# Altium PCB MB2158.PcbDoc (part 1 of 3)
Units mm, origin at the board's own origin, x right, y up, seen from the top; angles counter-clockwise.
Board outline 43 x 60 mm, 4 copper layers (Top Layer, Signal Layer 1, Signal Layer 2, Bottom Layer), stack 1.539 mm thick; 117 components, 89 nets, 427 pads, 621 vias.
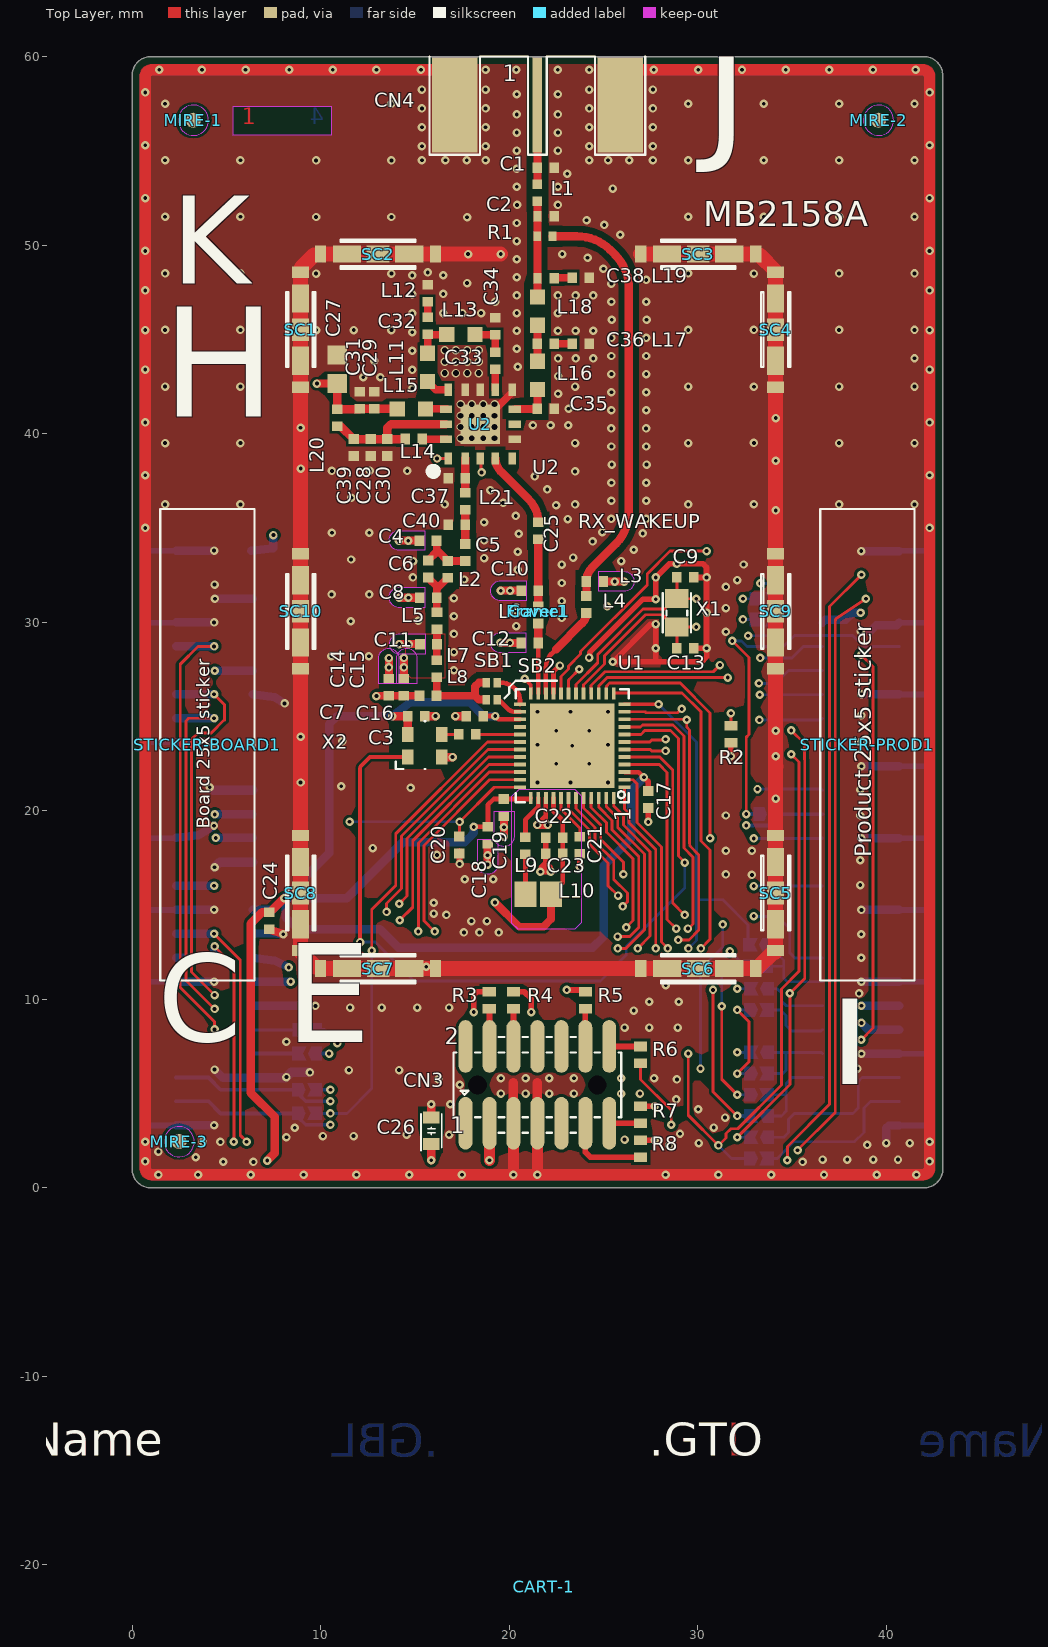
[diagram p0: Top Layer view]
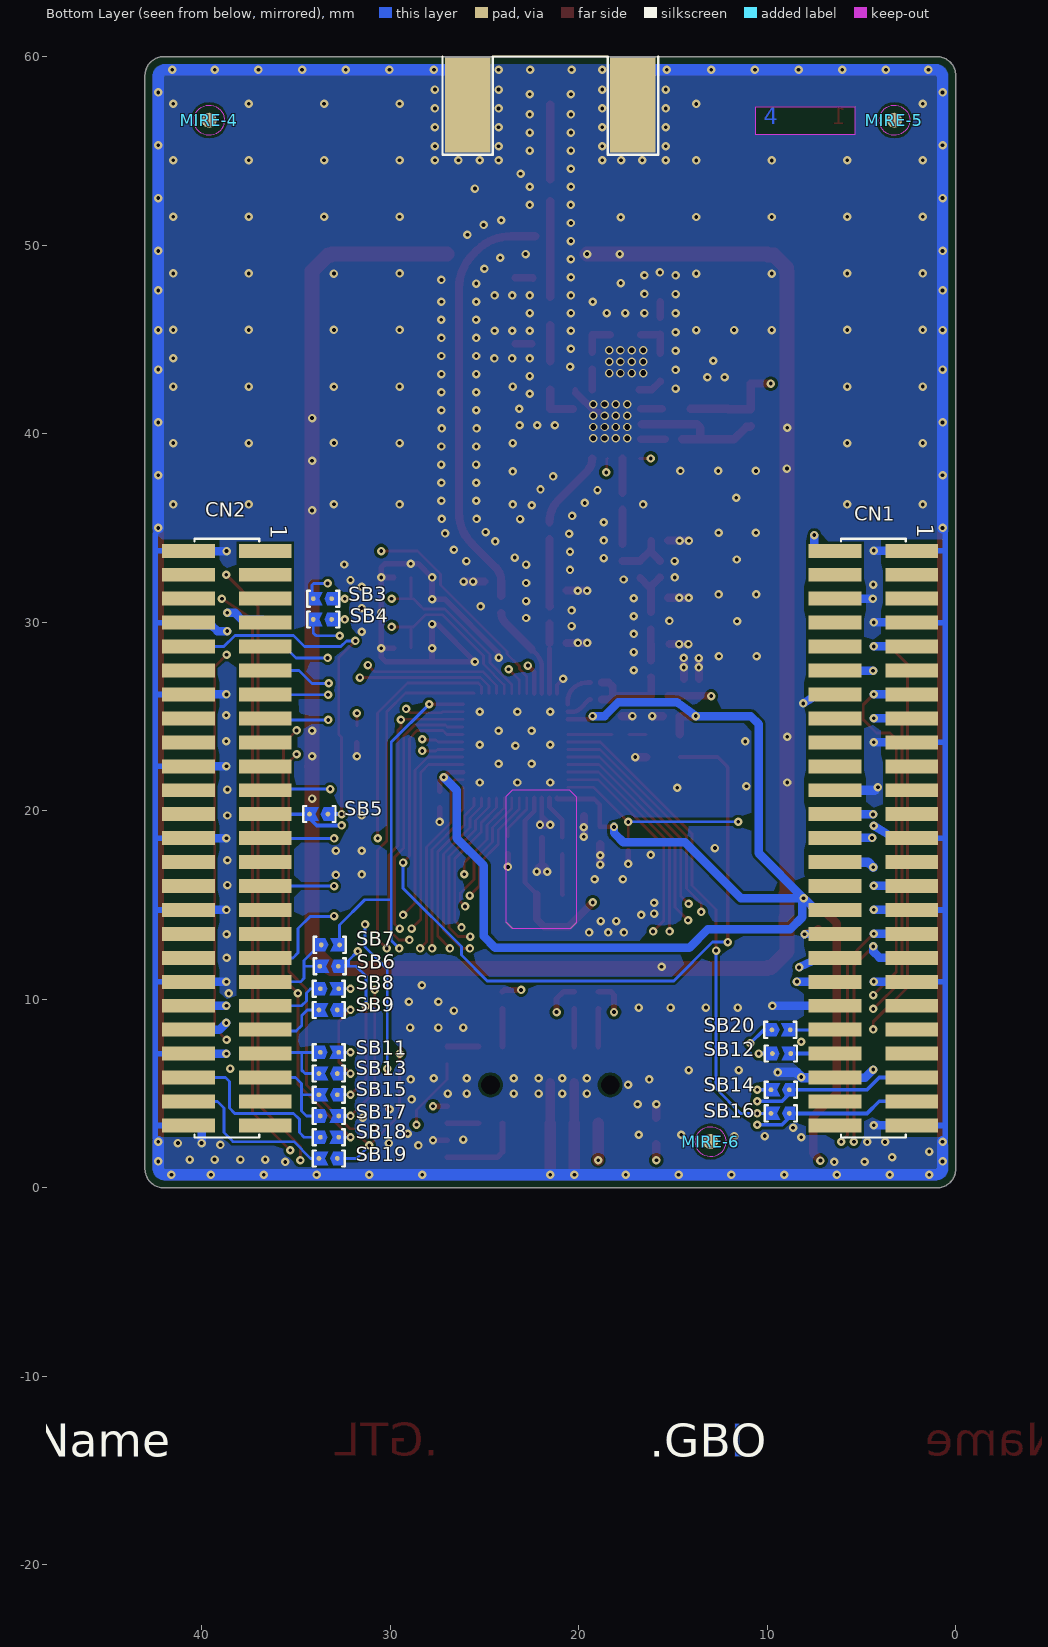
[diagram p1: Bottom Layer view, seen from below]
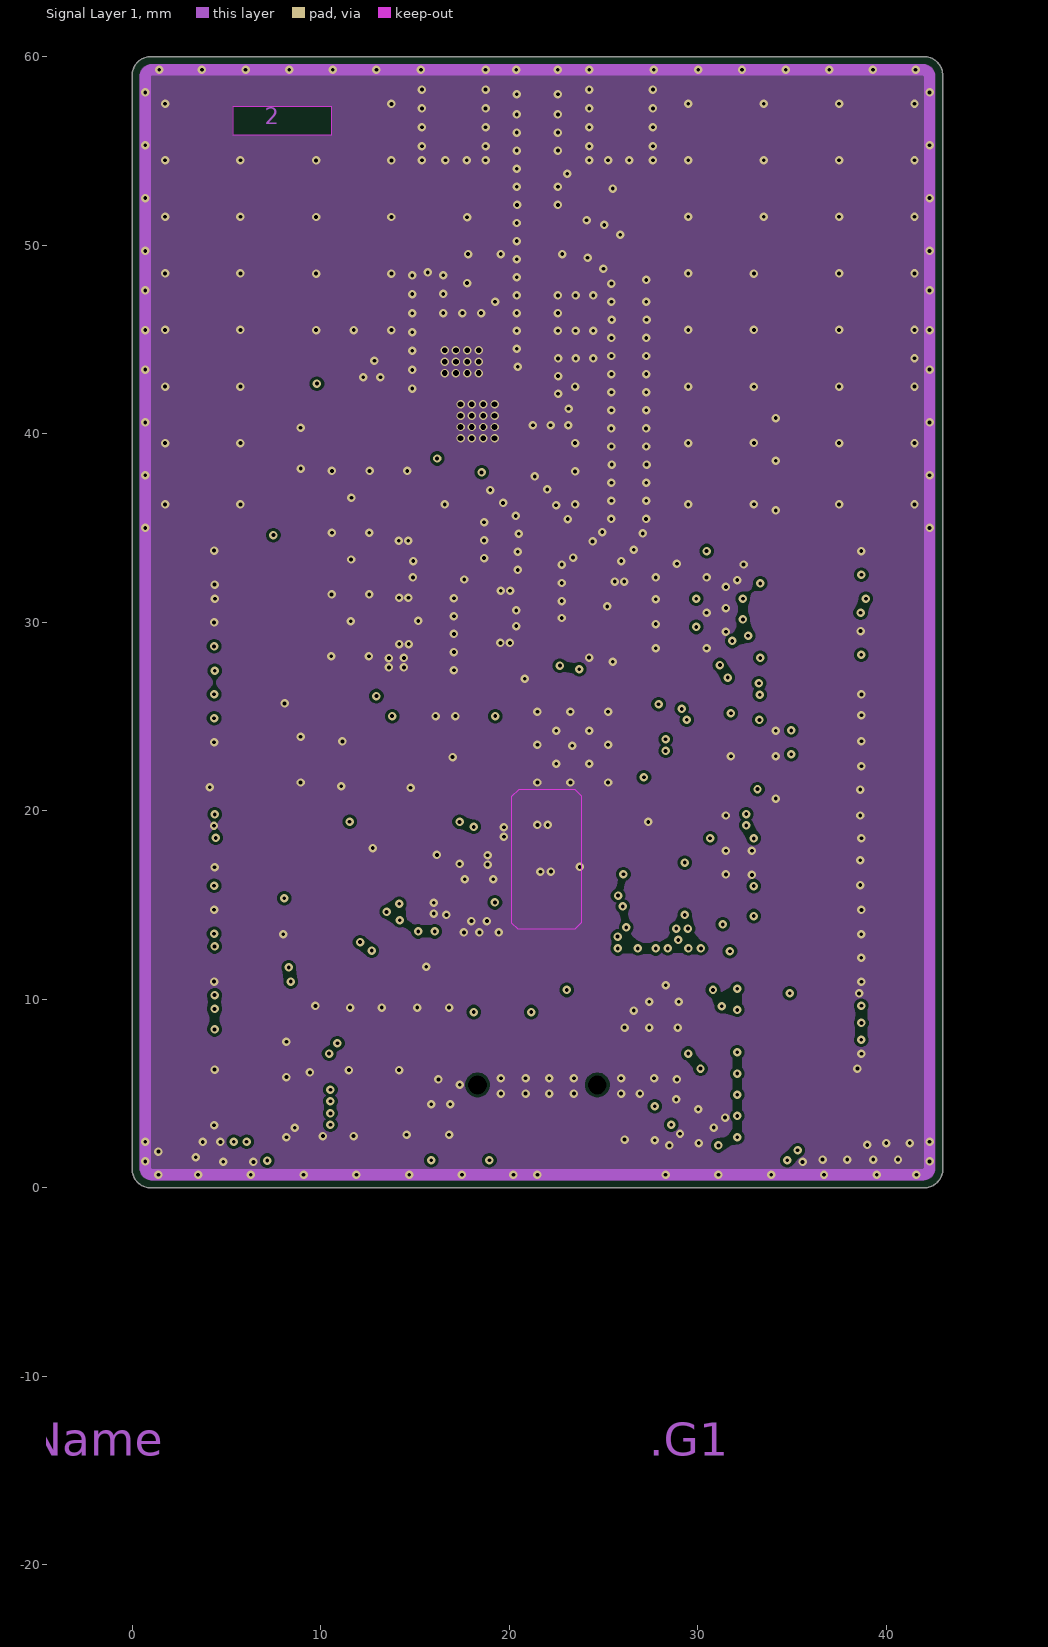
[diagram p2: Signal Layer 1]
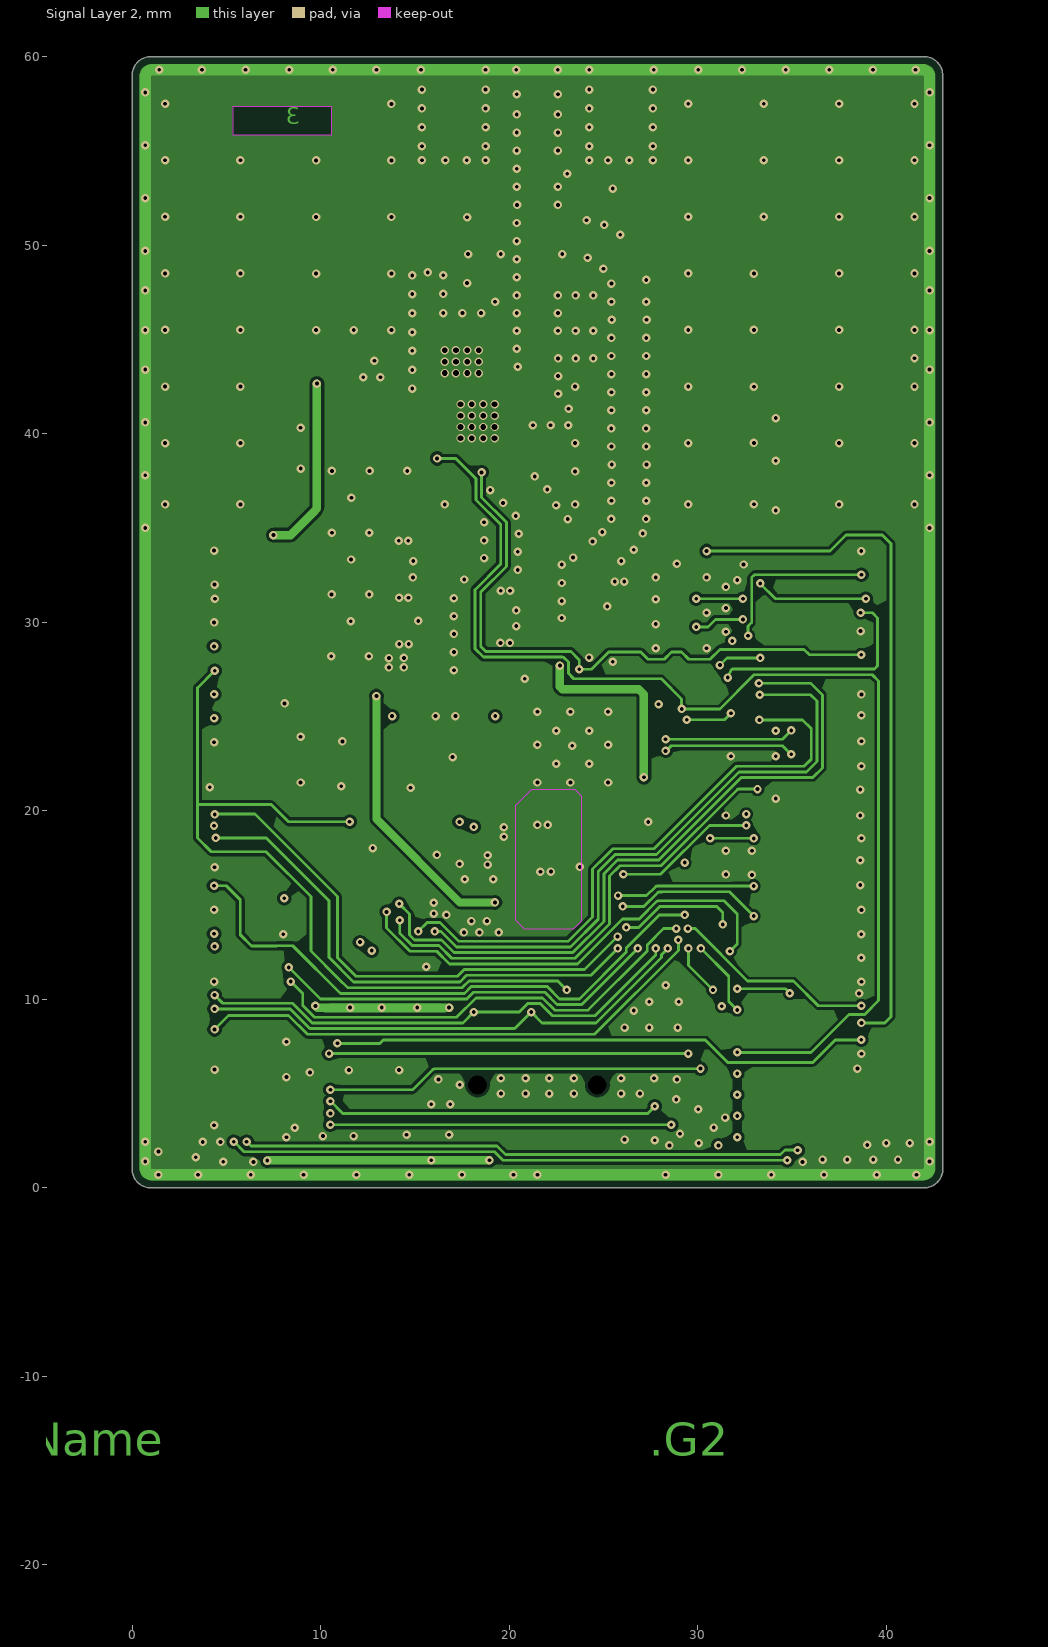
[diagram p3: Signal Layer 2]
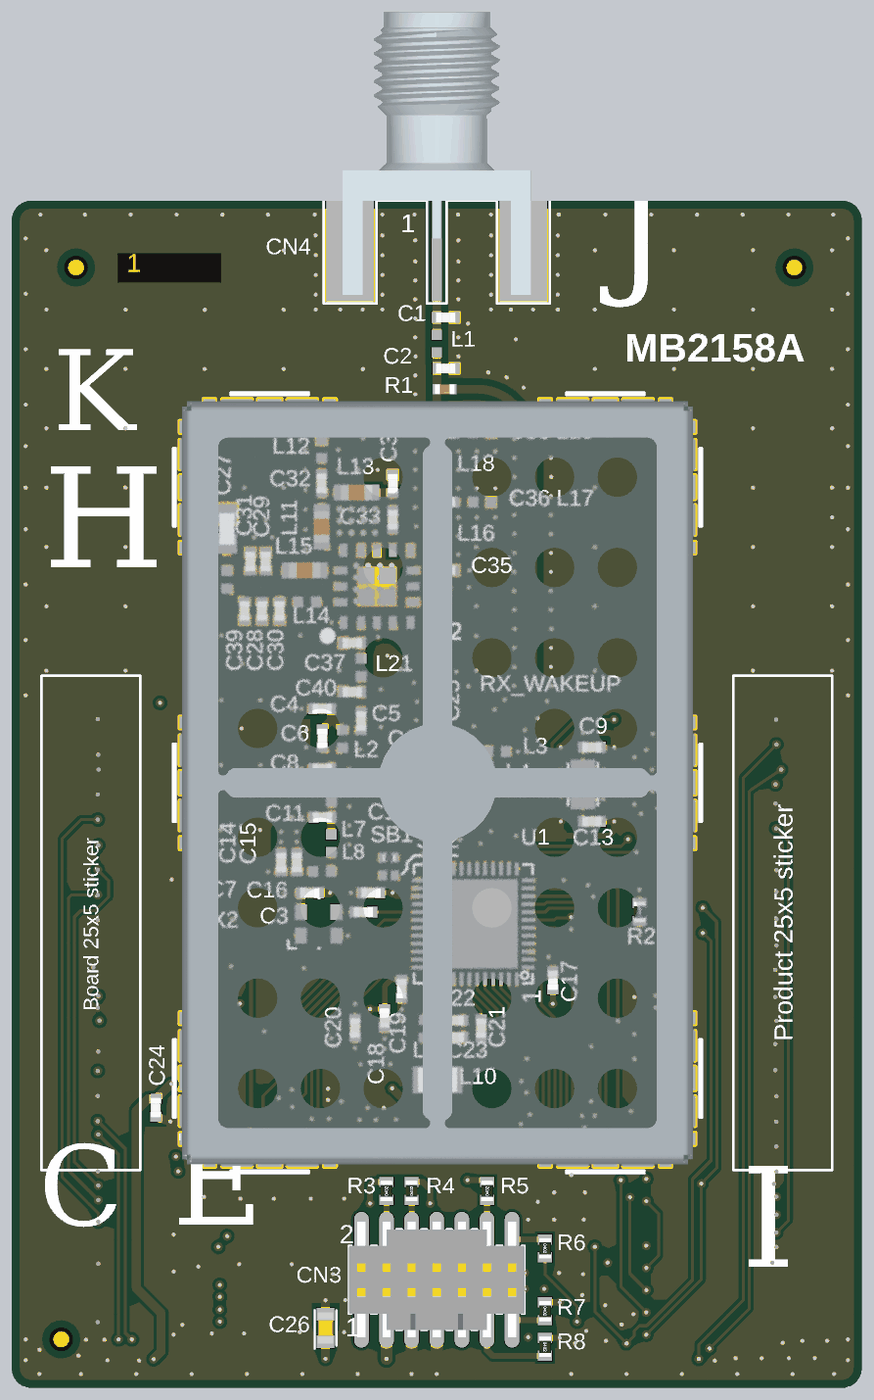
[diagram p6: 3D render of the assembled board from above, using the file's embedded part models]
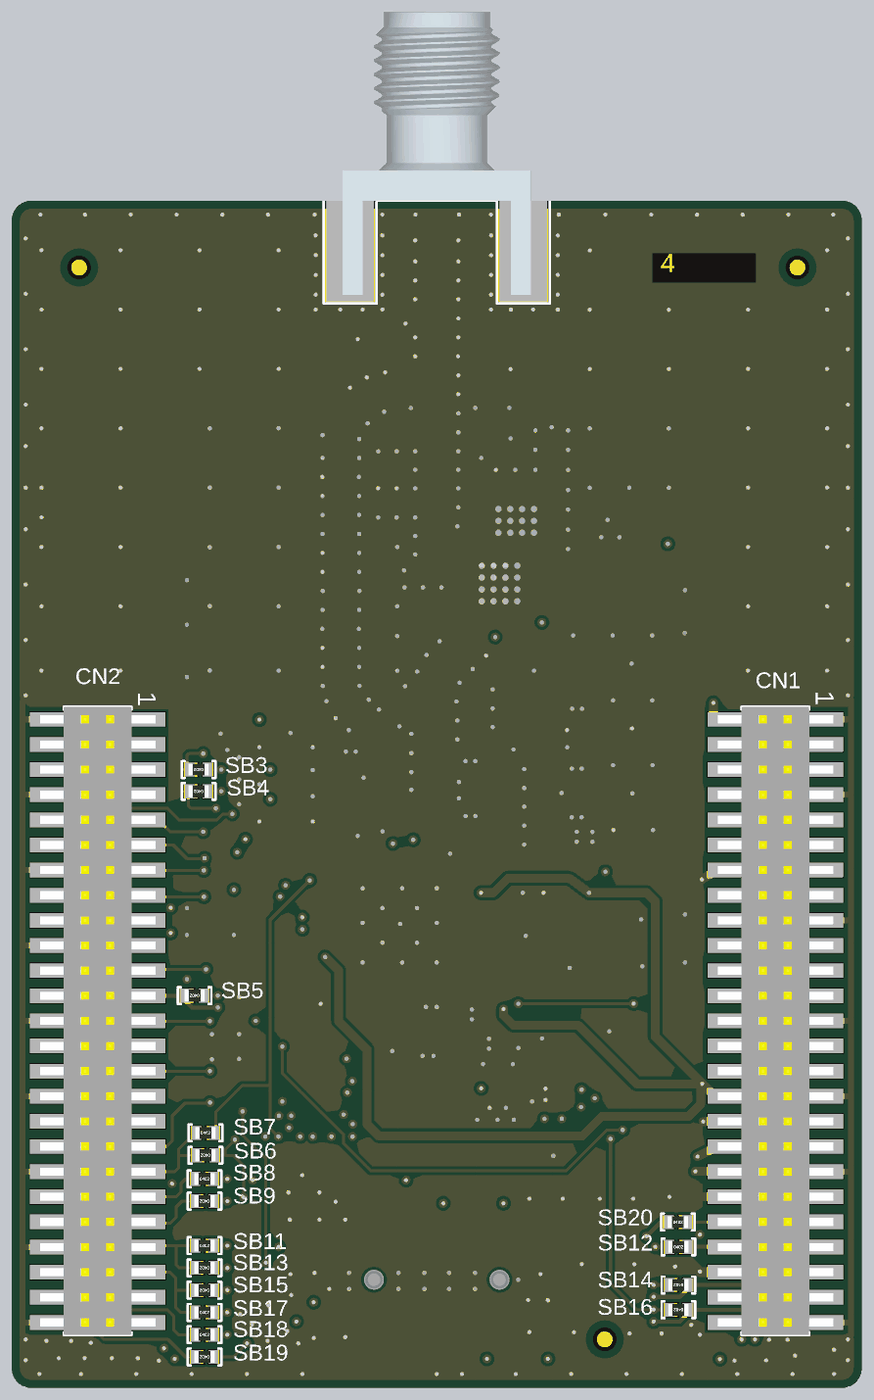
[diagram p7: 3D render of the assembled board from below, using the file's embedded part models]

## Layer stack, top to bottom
Top Solder: solder mask 0.0102, Solder Resist, Dk 3.5
Top Layer: signal copper 0.0406
Dielectric 1: core 0.254, FR4 VT-47, Dk 4
Signal Layer 1: signal copper 0.0178
Dielectric 2: core 0.9144, FR4 VT-47, Dk 4.3
Signal Layer 2: signal copper 0.0178
Dielectric 3: core 0.254, FR4 VT-47, Dk 4
Bottom Layer: signal copper 0.0406
Bottom Solder: solder mask 0.0102, Solder Resist, Dk 3.5

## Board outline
0,1 ccw(c1,1) 1,0 42,0 ccw(c42,1) 43,1 43,59 ccw(c42,59) 42,60 1,60 ccw(c1,59) 0,59

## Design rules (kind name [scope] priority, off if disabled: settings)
BoardOutlineClearance [All] p1: gap=0.4 ignorepadtopadclearanceinfootprint=FALSE
Clearance Clearance_Keepout [All vs IsKeepOut] p1: gap=0.15 ignorepadtopadclearanceinfootprint=TRUE except(0: Poly-Region)
Clearance Clearance_RF-50R [InNetClass('NC_RF-50R')] p2: gap=0.335 ignorepadtopadclearanceinfootprint=FALSE except(0.15: Arc-Arc Arc-Track Arc-SMDPad Arc-Via Track-Track Track-SMDPad Track-Via SMDPad-Via Via-Via Via-Fill Via-Region Via-Text Via-Hole; 0.2: SMDPad-SMDPad)
Clearance Clearance_Default_Same-net_GND [InNet('GND')] p3: gap=0.15 ignorepadtopadclearanceinfootprint=TRUE except(0: SMDPad-Via SMDPad-Hole Via-Via; 0.1: Arc-SMDPad Track-SMDPad Via-Hole; 0.12: SMDPad-SMDPad)
Clearance Clearance_Default_Same-net [All] p4: gap=0.15 ignorepadtopadclearanceinfootprint=TRUE except(0.1: Via-Via; 0.12: Arc-SMDPad Track-SMDPad SMDPad-SMDPad)
Clearance Clearance_Default [All] p5: gap=0.15 ignorepadtopadclearanceinfootprint=FALSE
ComponentClearance [All] p1: gap=0.165 collisioncheckmode=3 verticalgap=0.165 showdistances=FALSE
HoleSize [All] p1: absolutevalues=TRUE maxlimit=10 minlimit=0.025 maxpercent=80.000 minpercent=20.000
MinimumSolderMaskSliver [All] p1: minsoldermaskwidth=0.1
PlaneConnect [All] p1: planeconnectstyle=Relief reliefexpansion=0.508 reliefentries=4 reliefconductorwidth=0.21 reliefairgap=0.21
PolygonConnect PolygonConnect_PA [TouchesRoom('RoomDefinition')  or TouchesRoom('RoomDefinition_1') or TouchesRoom('RoomDefinition_2')or  TouchesRoom('RoomDefinition_3')or  TouchesRoom('RoomDefinition_4')] p1: connectstyle=Direct reliefconductorwidth=0.3 reliefentries=4 polygonreliefangle="90 Angle" airgapwidth=0.25
PolygonConnect [All] p2: thpad.connectstyle=Direct thpad.reliefconductorwidth=0.254 thpad.reliefentries=4 thpad.polygonreliefangle="90 Angle" thpad.airgapwidth=0.254 smdpad.connectstyle=NoConnect smdpad.reliefconductorwidth=0.254 smdpad.reliefentries=4 smdpad.polygonreliefangle="90 Angle" smdpad.airgapwidth=0.254 via.connectstyle=Direct via.reliefconductorwidth=0.254 via.reliefentries=4 via.polygonreliefangle="90 Angle" via.airgapwidth=0.254
RoomDefinition [False vs False] p1: confinementstyle=ConfineIn formatcopy=TRUE lockcomponents=FALSE outline 8.289,49.929 35.214,49.929 35.214,34.798 8.289,34.798
RoomDefinition RoomDefinition_3 [False vs False] p2: confinementstyle=ConfineIn formatcopy=TRUE lockcomponents=FALSE outline 33.125,34.4 35.139,34.4 35.139,26.625 33.125,26.625
RoomDefinition RoomDefinition_2 [False vs False] p3: confinementstyle=ConfineIn formatcopy=TRUE lockcomponents=FALSE outline 26.35,19.35 35.564,19.35 35.564,11 26.35,11
RoomDefinition RoomDefinition_1 [False vs False] p4: confinementstyle=ConfineIn formatcopy=TRUE lockcomponents=FALSE outline 7.925,34.4 9.939,34.4 9.939,26.625 7.925,26.625
RoomDefinition RoomDefinition_4 [False vs False] p5: confinementstyle=ConfineIn formatcopy=TRUE lockcomponents=FALSE outline 7.754,19.35 16.536,19.35 16.536,11 7.754,11
RoutingVias RoutingVias_Default [All] p1: holewidth=0.3 width=0.6 viastyle="Through Hole" minholewidth=0.3 minwidth=0.6 maxholewidth=0.3 maxwidth=0.6 useviatemplates=TRUE viatemplateguid#1={4832C824-464C-45B0-9914-ADACDA891A13} viatemplateguid#2={A0866A0D-D653-4B5A-8CD1-50116DFB51F8} viatemplatename#1=v45h20m0mx0 viatemplatename#2=v45h30m0mx0
SilkToSilkClearance [All] p1 off: silktosilkclearance=0.2
SilkToSolderMaskClearance [IsPad] p1 off: minsilkscreentomaskgap=0.2 clearancetoexposedcopper=TRUE
SolderMaskExpansion [All] p1: expansion=0.102 istentingtop=FALSE
ViasUnderSMD [InPadClass('PC__VIAS-IN-PAD')] p1: allowed=TRUE
Width Width_RF-50R [InNetClass('NC_RF-50R')] p1: maxlimit=0.45 minlimit=0.25 preferedwidth=0.254 toplayer_prefwidth=0.44 impedanceprofiledriven=TRUE impedanceprofileid={AD1550EC-3D0E-4E34-9E21-FD44D1EEEC04} impedanceprofilevalue=50.000000 minimp=50.000000 maximp=50.000000 favimp=50.000000
Width Width_Default [All] p2: maxlimit=10 minlimit=0.15 preferedwidth=0.2
24 further rules are at their usual default settings.

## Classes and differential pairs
pad class PC__VIAS-IN-PAD: U1- U1-49
net class NC_RF-50R: "ANT Path" NetC1_2 NetC4_2 NetC6_1 NetC11_2 NetC25_2 NetC35_2 NetC36_2 NetC37_2 NetL3_1 NetL7_1 NetSB1_1 NetSB2_1 "RX Path" "TX Path"

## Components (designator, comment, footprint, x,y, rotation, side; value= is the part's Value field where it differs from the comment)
C1 "Capacitor" C0402#1 21.95,54.1 r180 top value=TBD
C2 "Capacitor" C0402#2 21.95,51.525 r180 top value=TBD
C3 "Capacitor" C0402#1 17.787,24.05 r180 top value=1nF
C4 "Capacitor" C0402#1 15.7,34.325 r0 top value=TBD
C5 "Capacitor" C0402#1 17.675,33.7 r270 top value=TBD
C6 "Capacitor" C0402#1 15.711,32.825 r90 top value=TBD
C7 "Capacitor" C0402#1 15.077,25.025 r180 top value=10nF
C8 "Capacitor" C0402#1 15.711,31.3 r0 top value=TBD
C9 "Capacitor" C0402#1 29.35,32.375 r180 top value=6.8pF
C10 "Capacitor" C0402#1 21.1,31.675 r0 top value=TBD
C11 "Capacitor" C0402#1 15.725,28.841 r0 top value=TBD
C12 "Capacitor" C0402#1 21.09,28.9 r0 top value=TBD
C13 "Capacitor" C0402#1 29.35,28.625 r180 top value=6.8pF
C14 "Capacitor" C0402#1 13.625,26.55 r90 top value=100pF
C15 "Capacitor" C0402#1 14.42,26.555 r270 top value=100nF
C16 "Capacitor" C0402#1 18.175,25.025 r0 top value=100nF
C17 "Capacitor" C0402#1 27.375,20.6 r90 top value=100nF
C18 "Capacitor" C0402#1 18.857,18.696 r90 top value=4.7uF
C19 "Capacitor" C0402#1 19.725,20.175 r90 top value=100nF
C20 "Capacitor" C0402#1 17.365,18.183 r90 top value=100nF
C21 "Capacitor" C0402#1 23.75,18.175 r90 top value=220nF
C22 "Capacitor" C0402#1 22.391,18.572 r0 top value=4.7uF
C23 "Capacitor" C0402#1 22.391,17.722 r180 top value=100nF
C24 "Capacitor" C0402#1 7.286,14.165 r90 top value=4.7uF
C25 "Capacitor" C0402#1 21.55,34.85 r90 top value=2.2nF
C26 "Capacitor" C0603 15.875,3.025 r270 top value=1uF
C27 "Capacitor" GRM185C80J475ME11D 10.881,43.416 r90 top value=4.7uF
C28 "Capacitor" C0402#1 12.659,39.267 r270 top value=1nF
C29 "Capacitor" C0402#1 12.844,41.767 r90 top value=1uF
C30 "Capacitor" C0402#1 13.548,39.267 r270 top value=DNI
C31 "Capacitor" C0402#1 12.068,41.767 r90 top value=4.7nF
C32 "Capacitor" C0402#1 15.675,45.718 r270 top value=82pF
C33 "Capacitor" C0402#1 19.275,43.875 r90 top value=2.2nF
C34 "Capacitor" C0402#1 19.275,45.7 r270 top value=27pF
C35 "Capacitor" C0402#1 21.95,41.322 r180 top value=22pF
C36 "Capacitor" C0402#1 21.95,44.768 r180 top value=18pF
C37 "Capacitor" C0402#1 17.225,37.643 r0 top value=DNI
C38 "Capacitor" C0402#2 21.95,48.254 r180 top value=DNI
C39 "Capacitor" C0402#1 11.77,39.267 r270 top value=1uF
C40 "Capacitor" C0402#1 17.225,35.173 r0 top value=22pF
CART-1 "Comment" Sheetbox_4L2S -23.25,-26.5 r0 top
CN1 "FTSH-125-02-L-DV" CON_SAMTEC_FTSH-125-02-L-DV_INV 4.366,18.548 r270 bottom locked value="Header 25x2"
CN2 "FTSH-125-02-L-DV" CON_SAMTEC_FTSH-125-02-L-DV_INV 38.656,18.548 r270 bottom locked value="Header 25x2"
CN3 "Header 7x2" CON_SAMTEC_FTSH-107-01-L-DV-K-A 21.5,5.465 r0 top locked
CN4 "mmcx" CON_SMA-RF_CINCH_142-0701-851 21.5,60 r0 top
Cover1 "TopCover_WE-SHC Shielding Cabinet" 3600637250S 21.539,30.579 r90 top value=3600637250S
Frame1 "Frame_WE-SHC Shielding Cabinet" 3610637256S 21.539,30.579 r90 top value=3610637256S
L1 "Inductor" L0402#1 21.5,52.775 r90 top value=0R
L2 "Inductor" L0402#2 16.736,32.8 r90 top value=TBD
L3 "Inductor" L0402#2 24.55,32.16 r0 top value=TBD
L4 "Inductor" L0402#2 24.1,30.941 r90 top value=TBD
L5 "Inductor" L0402#2 16.175,30.075 r90 top value=TBD
L6 "Inductor" L0402#2 21.539,30.384 r90 top value=TBD
L7 "Inductor" L0402#2 16.161,27.525 r90 top value=TBD
L8 "Inductor" L0402#2 15.698,26.1 r0 top value=TBD
L9 "Inductor" L0402#2 20.866,18.147 r90 top value=TBD
L10 "Inductor" LQM21FN_70-IPC_C 21.542,15.569 r180 top value=10µH
L11 "Inductor" C0603_coilcraft 15.674,43.518 r90 top value=7.5nH
L12 "Inductor" L0402#2 15.675,47.45 r90 top value=2.7nH
L13 "Inductor" C0603_coilcraft 17.443,45.25 r0 top value=27nH
L14 "Inductor" L0402#2 14.945,39.717 r180 top value=15nH
L15 "Inductor" C0603_coilcraft 14.818,41.317 r180 top value=10nH
L16 "Inductor" C0603_coilcraft 21.5,43.092 r90 top value=47nH
L17 "Inductor" L0402#2 23.8,44.768 r0 top value=4.7nH
L18 "Inductor" C0603_coilcraft 21.5,46.502 r90 top value=0R
L19 "Inductor" L0402#2 23.8,48.282 r0 top value=DNI
L20 "Inductor" L0402#2 10.881,40.842 r90 top
L21 "Inductor" L0402#2 17.675,36.41 r90 top value=27nH
MIRE-1 "Comment" MIRE_PLACE_SMD_0P8MM 3.25,56.625 r0 top
MIRE-2 "Comment" MIRE_PLACE_SMD_0P8MM 39.594,56.625 r0 top
MIRE-3 "Comment" MIRE_PLACE_SMD_0P8MM 2.5,2.45 r0 top
MIRE-4 "Comment" MIRE_PLACE_SMD_0P8MM 39.594,56.625 r180 bottom
MIRE-5 "Comment" MIRE_PLACE_SMD_0P8MM 3.25,56.625 r180 bottom
MIRE-6 "Comment" MIRE_PLACE_SMD_0P8MM 13,2.45 r180 bottom
R1 "Resistor" GRM155--GJM155-0_05-MFG 21.9,50.475 r0 top value=0
R2 "Resistor" R0402 31.763,24.05 r90 top value=100K
R3 "Resistor" R0402 18.95,9.95 r90 top value=47R
R4 "Resistor" R0402 20.225,9.95 r90 top value=47R
R5 "Resistor" R0402 24.05,9.95 r90 top value=47R
R6 "Resistor" R0402 26.975,7.05 r270 top value=47R
R7 "Resistor" R0402 26.975,3.875 r270 top value=47R
R8 "Resistor" R0402 26.975,2.075 r270 top value=47R
SB1 "SB_ON" SOLDER-BRIDGE_R0201_0R 19.075,26.8 r180 top
SB2 "SB_ON" SOLDER-BRIDGE_R0201_0R 19.075,25.9 r180 top value=0R
SB3 "SB_ON" SOLDER-BRIDGE_R0402-0R 33.55,31.25 r0 bottom
SB4 "SB_ON" SOLDER-BRIDGE_R0402-0R 33.55,30.15 r0 bottom
SB5 "SB_ON" SOLDER-BRIDGE_R0402-0R 33.75,19.825 r0 bottom
SB6 "SB_ON" SOLDER-BRIDGE_R0402-0R 33.202,11.752 r0 bottom
SB7 "SB_ON" SOLDER-BRIDGE_R0402-0R 33.202,12.888 r180 bottom
SB8 "SB_ON" SOLDER-BRIDGE_R0402-0R 33.25,10.563 r180 bottom
SB9 "SB_ON" SOLDER-BRIDGE_R0402-0R 33.25,9.437 r0 bottom
SB11 "SB_ON" SOLDER-BRIDGE_R0402-0R 33.25,7.187 r180 bottom
SB12 "SB_ON" SOLDER-BRIDGE_R0402-0R 9.275,7.125 r180 bottom
SB13 "SB_ON" SOLDER-BRIDGE_R0402-0R 33.25,6.062 r0 bottom
SB14 "SB_ON" SOLDER-BRIDGE_R0402-0R 9.275,5.2 r0 bottom
SB15 "SB_ON" SOLDER-BRIDGE_R0402-0R 33.25,4.938 r0 bottom
SB16 "SB_ON" SOLDER-BRIDGE_R0402-0R 9.275,3.95 r0 bottom
SB17 "SB_ON" SOLDER-BRIDGE_R0402-0R 33.25,3.812 r180 bottom
SB18 "SB_ON" SOLDER-BRIDGE_R0402-0R 33.25,2.688 r180 bottom
SB19 "SB_ON" SOLDER-BRIDGE_R0402-0R 33.25,1.562 r0 bottom
SB20 "SB_ON" SOLDER-BRIDGE_R0402-0R 9.299,8.38 r180 bottom
SC1 "Shield-clip" 3690000 8.939,45.519 r90 top value=36900000
SC2 "Shield-clip" 3690000 13.048,49.529 r0 top value=36900000
SC3 "Shield-clip" 3690000 30.029,49.529 r0 top value=36900000
SC4 "Shield-clip" 3690000 34.139,45.52 r270 top value=36900000
SC5 "Shield-clip" 3690000 34.139,15.638 r270 top value=36900000
SC6 "Shield-clip" 3690000 30.029,11.629 r0 top value=36900000
SC7 "Shield-clip" 3690000 13.049,11.629 r0 top value=36900000
SC8 "Shield-clip" 3690000 8.939,15.638 r90 top value=36900000
SC9 "Shield-clip" 3690000 34.139,30.579 r270 top value=36900000
SC10 "Shield-clip" 3690000 8.939,30.579 r90 top value=36900000
STICKER-BOARD1 "Comment" STICKER_BOARD_25X5 4,23.5 r90 top
STICKER-PROD1 "Comment" STICKER_PRODUCT_25X5 39,23.5 r90 top
U1 "STM32WL33" ICC_QFN48-EPAD-4P5X4P5_6X6_P040 23.35,23.45 r180 top
U2 "SKY66121-11" SKY65367-11 16.775,38.68 r90 top
X1 "XTAL_2_PINS" CRY_NX2012SA_2P 28.9,30.5 r90 top value=32.768kHz
X2 "48MHz" NT2016SJA 14.627,22.85 r0 top

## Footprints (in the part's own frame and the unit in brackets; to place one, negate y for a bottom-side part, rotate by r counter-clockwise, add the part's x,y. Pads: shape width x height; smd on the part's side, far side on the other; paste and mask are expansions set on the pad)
3690000 [mm]
  rect 0.6x0.9 smd: 1(-3.05,0) 1(3.05,0)
  rect 1.5x0.9 smd: 1(-1.65,0) 1(1.65,0)
  rect 1.2x0.9 smd: 1(0,0)
  silkscreen extent -1.98,-0.78 1.98,0.78, body extent -3.25,-0.41 3.25,0.41, height 1.28
3600637250S [mm]
  body extent -19.28,-12.93 19.28,12.93, height 6.2
3610637256S [mm]
  body extent -19.05,-12.7 19.05,12.7, height 6
C0402#1 [mm]
  rect 0.51x0.56 smd mask+0.05: 1(-0.45,0) 2(0.45,0)
  body extent -0.5,-0.3 0.5,0.3, height 0.4
C0402#2 [mm]
  rect 0.51x0.56 smd mask+0.05: 1(-0.45,0)
  rect 0.44x0.56 smd mask+0.05: 2(0.45,0)
  body extent -0.5,-0.3 0.5,0.3, height 0.4
C0603 [mm]
  rect 0.64x0.89 smd mask+0.05: 1(-0.7,0) 2(0.7,0)
  silkscreen extent -0.9,-0.55 1.05,0.55, body extent -0.9,-0.5 0.9,0.5, height 1.4
C0603_coilcraft [mm]
  rect 0.8x0.8 smd mask+0.05: 1(-0.75,0) 2(0.75,0)
  body extent -0.9,-0.5 0.9,0.5, height 1.4
CON_SAMTEC_FTSH-107-01-L-DV-K-A [mm] "MCD-01959"
  oval 0.74x2.79 smd mask+0.05: 1(-3.81,-2.035) 2(-3.81,2.035) 3(-2.54,-2.035) 4(-2.54,2.035) 5(-1.27,-2.035) 6(-1.27,2.035) 7(0,-2.035) 8(0,2.035) 9(1.27,-2.035) 10(1.27,2.035) 11(2.54,-2.035) 12(2.54,2.035) 13(3.81,-2.035) 14(3.81,2.035)
  round 0 hole 1 unplated paste-2539.97 mask+0.05: NPTH1(-3.175,0) NPTH2(3.175,0)
  silkscreen extent -4.44,-2.54 4.45,2.54, body extent -4.44,-2.92 4.45,2.92, height 6.12
CON_SAMTEC_FTSH-125-02-L-DV_INV [mm]
  rect 0.74x2.79 smd mask+0.05: 1(-15.24,2.035) 2(-15.24,-2.035) 3(-13.97,2.035) 4(-13.97,-2.035) 5(-12.7,2.035) 6(-12.7,-2.035) 7(-11.43,2.035) 8(-11.43,-2.035) 9(-10.16,2.035) 10(-10.16,-2.035) 11(-8.89,2.035) 12(-8.89,-2.035) 13(-7.62,2.035) 14(-7.62,-2.035) 15(-6.35,2.035) 16(-6.35,-2.035) 17(-5.08,2.035) 18(-5.08,-2.035) 19(-3.81,2.035) 20(-3.81,-2.035) 21(-2.54,2.035) 22(-2.54,-2.035) 23(-1.27,2.035) 24(-1.27,-2.035) 25(0,2.035) 26(0,-2.035) 27(1.27,2.035) 28(1.27,-2.035) 29(2.54,2.035) 30(2.54,-2.035) 31(3.81,2.035) 32(3.81,-2.035) 33(5.08,2.035) 34(5.08,-2.035) 35(6.35,2.035) 36(6.35,-2.035) 37(7.62,2.035) 38(7.62,-2.035) 39(8.89,2.035) 40(8.89,-2.035) 41(10.16,2.035) 42(10.16,-2.035) 43(11.43,2.035) 44(11.43,-2.035) 45(12.7,2.035) 46(12.7,-2.035) 47(13.97,2.035) 48(13.97,-2.035) 49(15.24,2.035) 50(15.24,-2.035)
  silkscreen extent -15.87,-1.71 15.88,1.71, body extent -15.87,-2.92 15.88,2.92, height 4.82
CON_SMA-RF_CINCH_142-0701-851 [mil] "MCD-02072"
  rect 20.08x200 smd mask+1.97: 1(0,-100)
  rect 95x200 smd mask+1.97: 2(172.48,-100) 3(-172.48,-100)
  rect 95x200 smd far side mask+1.97: 4(-172.48,-100) 5(172.48,-100)
  silkscreen extent -225,-205 225,0, body extent -189,-187 189,376, height 161
CRY_NX2012SA_2P [mm]
  rect 1x1.25 smd mask+0.05: 1(-0.75,0) 2(0.75,0)
  silkscreen extent -1.05,-0.75 1.05,0.75, body extent -1.05,-0.63 1.05,0.63, height 0.6
GRM155--GJM155-0_05-MFG [mm]
  rect 0.4x0.5 smd paste+0 mask+0: 1(-0.4,0) 2(0.4,0)
  body extent -0.7,-0.38 0.7,0.38, height 0.25
GRM185C80J475ME11D [mm] "4.7uF 0603"
  rect 1x1.02 smd: 1(-0.759,0) 2(0.759,0)
  body extent -0.8,-0.4 0.8,0.4, height 0.55
ICC_QFN48-EPAD-4P5X4P5_6X6_P040 [mm] "MCD-03488"
  rect 0.65x0.2 smd mask+0.05: 1(-2.775,2.2) 2(-2.775,1.8) 3(-2.775,1.4) 4(-2.775,1) 5(-2.775,0.6) 6(-2.775,0.2) 7(-2.775,-0.2) 8(-2.775,-0.6) 9(-2.775,-1) 10(-2.775,-1.4) 11(-2.775,-1.8) 12(-2.775,-2.2) 25(2.775,-2.2) 26(2.775,-1.8) 27(2.775,-1.4) 28(2.775,-1) 29(2.775,-0.6) 30(2.775,-0.2) 31(2.775,0.2) 32(2.775,0.6) 33(2.775,1) 34(2.775,1.4) 35(2.775,1.8) 36(2.775,2.2)
  rect 0.2x0.65 smd mask+0.05: 13(-2.2,-2.775) 14(-1.8,-2.775) 15(-1.4,-2.775) 16(-1,-2.775) 17(-0.6,-2.775) 18(-0.2,-2.775) 19(0.2,-2.775) 20(0.6,-2.775) 21(1,-2.775) 22(1.4,-2.775) 23(1.8,-2.775) 24(2.2,-2.775) 37(2.2,2.775) 38(1.8,2.775) 39(1.4,2.775) 40(1,2.775) 41(0.6,2.775) 42(0.2,2.775) 43(-0.2,2.775) 44(-0.6,2.775) 45(-1,2.775) 46(-1.4,2.775) 47(-1.8,2.775) 48(-2.2,2.775)
  rect 4.5x4.5 smd mask+0.05: 49(0,0)
  silkscreen extent -3,-3 3,3, body extent -3,-3 3,3, height 0.91
L0402#1 [mm]
  rect 0.51x0.51 smd mask+0.05: 1(-0.45,0) 2(0.45,0)
  body extent -0.5,-0.3 0.5,0.3, height 0.51
L0402#2 [mm]
  rect 0.51x0.56 smd mask+0.05: 1(-0.45,0) 2(0.45,0)
  body extent -0.5,-0.3 0.5,0.3, height 0.51
LQM21FN_70-IPC_C [mm]
  rect 1.154x1.356 smd paste+0 mask+0: 1(-0.676,0) 2(0.676,0)
  body extent -1.35,-0.82 1.35,0.82, height 0.25
MIRE_PLACE_SMD_0P8MM [mm]
  round 0.8 smd paste-10 mask+0.2: 1(0,0)
  Top Layer keep-out circle w0.01: c0,0 r0.804
NT2016SJA [mm] "MCD-02262"
  rect 0.6x0.8 smd mask+0.038: 1(0,0) 2(1.8,0) 3(1.8,1.2) 4(0,1.2)
  silkscreen extent -0.63,-0.64 0.94,1.9, body extent 0.03,-0.2 1.83,1.35, height 0.25
R0402 [mm]
  rect 0.51x0.7 smd mask+0.05: 1(-0.45,0) 2(0.45,0)
  body extent -0.52,-0.3 0.52,0.3, height 0.4
Sheetbox_4L2S [mil] "Sheetbox 4 layers / 2 silkscreens"
  round 20 on Mech16: 1(813.78,210.69) 1(2736.9,210.69)
SKY65367-11 [mm] "QFN, 16-Leads, Body 4.00x4.00mm, Pitch 0.80mm, Thermal Pad 2.00x2.00mm, IPC Medium Density"
  rect 0.65x0.4 smd paste+0 mask+0.05: 1(0,0) 2(0,-0.9) 3(0,-1.7) 4(0,-2.5) 5(0,-3.4) 9(3.65,-3.4) 10(3.65,-2.5) 11(3.65,-1.7) 12(3.65,-0.9) 13(3.65,0)
  rect 0.4x0.65 smd paste+0 mask+0.05: 6(1.025,-3.525) 7(1.825,-3.525) 8(2.625,-3.525) 14(2.625,0.125) 15(1.825,0.125) 16(1.025,0.125)
  rect 2.1x2.1 smd paste-2539.97 mask-0.05: 17(1.825,-1.7)
  silkscreen extent -0.87,0.6 -0.48,1, body extent -0.2,-3.73 3.8,0.27, height 0.9
SOLDER-BRIDGE_R0201_0R [mm] "MCD-03219"
  rect 0.4x0.5 smd mask+0.05: 1(-0.3,0) 2(0.3,0)
  body extent -0.32,-0.17 0.32,0.17, height 0.26
SOLDER-BRIDGE_R0402-0R [mil] "MCD-01619"
  round 10 smd paste-393.7: 1(-17.72,0) 2(20.67,0)
  Top Layer region: 1.48,13.78 8.37,0 1.48,-13.78 30.51,-13.78 30.51,13.78
  Top Layer region: -30.51,-13.78 -30.51,13.78 -8.86,13.78 -2.95,0 -8.86,-13.78
  silkscreen extent -33,-17 33,17, body extent -20,-12 20,12, height 14
STICKER_BOARD_25X5 [mm] "Sticker to mention board reference + serial number"
  silkscreen extent -12.5,-2.5 12.5,2.5
STICKER_PRODUCT_25X5 [mm] "Sticker to mention board CPN code"
  silkscreen extent -12.5,-2.5 12.5,2.5

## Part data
C1 C2: library part MCD-01600, "Capacitor, MLCC, 1pF, 50V, NPO, +/-0.1pF, 0402, T=0.5mm", Manufacturer=YAGEO, Package=0402
C3: library part MCD-03555, "Capacitor, MLCC, 1nF, 50V, C0G, +/-0.1pF, 0402, T=0.5mm", Manufacturer=MURATA, Manufacturer_Part_Number=GRM1555C1H102JA01, Package=0402
C4: library part MCD-03448, "Capacitor, MLCC, 2.7pF, 50V, C0G, +/-0.05pF, C0G, 0402, T=0.5mm", Manufacturer=MURATA, Package=0402
C5: library part MCD-03446, "Capacitor, MLCC, 100pF, 50V, COG, 1%, 0402, T=0.5mm", Manufacturer=MURATA, Package=0402
C6: library part MCD-02065, "Capacitor, Monolithic CC, 1.2pF, 50V, +/-0.05pf, 0402, T=0.5mm", Manufacturer=MURATA, Package=0402
C7: library part MCD-03555, "Capacitor, MLCC, 10nF, 50V, COG, +/-1%, 0402, T=0.5mm", Manufacturer=MURATA, Manufacturer_Part_Number=GRM1555C1E103JE01, Package=0402
C8: library part MCD-01374, "Capacitor, MLCC, 5.6pF, 50V, NPO, +/-0.1pF, 0402, T=0.5mm", Manufacturer=YAGEO, Package=0402
C9 C13: library part MCD-03452, "Capacitor, MLCC, 6.8pF, ±0.05pF, C0G, 50V, 0402, T=0.5mm", Manufacturer=MURATA, Manufacturer_Part_Number=GJM1555C1H6R8WB01, Package=0402
C10: library part MCD-02994, "Capacitor, MLCC, 1.5pF, 50V, C0G, +/-0.25pF, 0402, T=0.5mm", Manufacturer=MURATA, Package=0402
C11: library part MCD-03555, "Capacitor, MLCC, 5.3pF, 50V, C0G, +/-0.1pF, 0402, T=0.5mm", Manufacturer=MURATA, Package=0402
C12: library part MCD-02215, "Capacitor, MLCC, 0.5pF, 50V, C0G, +/-0.1pF, 0402, T=0.5mm", Manufacturer=MURATA, Package=0402
C14: library part MCD-03446, "Capacitor, MLCC, 100pF, 50V, COG, 1%, 0402, T=0.5mm", Manufacturer=MURATA, Manufacturer_Part_Number=GCM1555C1H101FA16, Package=0402
C15 C16 C17 C19 C23: library part MCD-03442, "Capacitor, MLCC, 100nF, +/-10%, X7R, 25V, 0402, T=0.5mm", Manufacturer=MURATA, Manufacturer_Part_Number=GRM155R71E104KE14D, Package=0402
C18 C22 C24: library part MCD-03431, "Capacitor, MLCC, 4.7uF, X5R, 10 V, 0402, ± 20%, T=0.5mm", Manufacturer=MURATA, Manufacturer_Part_Number=GRM155R61A475MEAAD, Package=0402
C20: library part MCD-00006, "Capacitor, MLCC, 100nF, 16V, X7R, +/-10%, 0402, T=0.5mm", Alternate_Manufacturer=MURATA, Alternate_Manufacturer_Part_Number=GCM155R71C104KA55D, Manufacturer=YAGEO, Manufacturer_Part_Number=CC0402KRX7R7BB104, Package=C0402
C21: library part MCD-03077, "Capacitor, MLCC, 220nF, 35V, X6S, +/-10%, 0402, T=0.5mm", Manufacturer=MURATA, Manufacturer_Part_Number=GRM155C8YA224KE01D, Package=0402
C25 C33: library part MCD-03431, "Capacitor, MLCC,  2.2nF, X5R, 10 V, 0402, ± 20%, T=0.5mm", Manufacturer=MURATA, Manufacturer_Part_Number=GRM155R71H222KA01, Package=0402
C26: library part MCD-00010, "Capacitor, MLCC, 1uF, 16V, X5R, 10%, 0603, T=0,8mm", Manufacturer=YAGEO, Manufacturer_Part_Number=CC0603KRX5R7BB105, Package=C0603
C27: library part MCD-03431, "Capacitor, MLCC,  4.7uF, X5R, 10 V, 0402, ± 20%, T=0.5mm", Manufacturer=MURATA, Manufacturer_Part_Number=GRM185C80J475ME11, Package=0603
C28: library part MCD-03431, "Capacitor, MLCC,  1nF, X5R, 10 V, 0402, ± 20%, T=0.5mm", Manufacturer=MURATA, Manufacturer_Part_Number=GRM1555C1H102JA01, Package=0402
C29 C39: library part MCD-03431, "Capacitor, MLCC,  1uF, X5R, 10 V, 0402, ± 20%, T=0.5mm", Manufacturer=MURATA, Manufacturer_Part_Number=GRT155R60J105KE01, Package=0402
C30 C37 C38: library part MCD-03431, Manufacturer=MURATA, Package=0402
C31: library part MCD-03431, "Capacitor, MLCC,  4.7nF, X5R, 10 V, 0402, ± 20%, T=0.5mm", Manufacturer=MURATA, Manufacturer_Part_Number=GRM155R71H472KA01, Package=0402
C32: library part MCD-03431, "Capacitor, MLCC,  82pF, X5R, 10 V, 0402, ± 20%, T=0.5mm", Manufacturer=MURATA, Manufacturer_Part_Number=GCM1555C1H820JA16, Package=0402
C34: library part MCD-03431, "Capacitor, MLCC,  27pF, X5R, 10 V, 0402, ± 20%, T=0.5mm", Manufacturer=MURATA, Manufacturer_Part_Number=GJM1555C1H270JB01, Package=0402
C35 C40: library part MCD-03431, "Capacitor, MLCC,  22pF, X5R, 10 V, 0402, ± 20%, T=0.5mm", Manufacturer=MURATA, Manufacturer_Part_Number=GJM1555C1H220JB01, Package=0402
C36: library part MCD-03431, "Capacitor, MLCC,  18pF, X5R, 10 V, 0402, ± 20%, T=0.5mm", Manufacturer=MURATA, Manufacturer_Part_Number=GJM1555C1H180JB01, Package=0402
CART-1: library part MCD-00279
CN1 CN2: library part MCD-02746, "Header, 25x2, 12.7mm, VR, SMD, T=4.83mm", Manufacturer=SAMTEC
CN3: library part MCD-01531, "Header, 7x2, 1.27mm, VR, T=5.97mm, FTSH series STDC14 without Alignment Pin", Manufacturer=SAMTEC, Manufacturer_Part_Number=FTSH-107-01-L-DV-K
CN4: library part MCD-02072, "Jack_SMA, VR, PCB edge, 50R, T=7.92mm", Alternate_Manufacturer=N/A, Manufacturer=CINCH, Manufacturer_Part_Number=142-0701-851
Cover1: "two-piece frame 37.7*25*5.8 mm", Manufacturer="Wurth Elektronik", Manufacturer_Part_Number=3600637250S
Frame1: "two-piece frame 37.7*25*5.8 mm", Manufacturer="Wurth Elektronik", Manufacturer_Part_Number=3610637256S
L1: library part MCD-01937, "Resistor, 0R, 0402, +/-5%, 1/16W", Manufacturer=YAGEO, Manufacturer_Part_Number=RC0402JR-070RL, Package=0402
L2: library part MCD-03460, "Inductor, Wire-wound, 5.6nH, ±0.1nH, 1770mA, 40mR, 0402, T=0.5mm", Manufacturer=MURATA, Package=0402
L3: library part MCD-03462, "Inductor, MLCC, 5.6nH, ±0.3nH, 650mA, 180mR, 0402, T=0.5mm", Manufacturer=MURATA, Package=0402
L4: library part MCD-03461, "Inductor, 6.8nH, +/-3%, 0.6A, 220mR, 0402, T=0.5mm"
L5: library part MCD-03459, "Inductor, Wire-wound, 6.2nH, ±0.1nH, 1600mA, 56mR, 0402, T=0.5mm", Manufacturer=MURATA, Package=0402
L6: library part MCD-01766, "Inductor, 15nH, +/-2%, Itemp=460mA max, 0R16, 0402, T= 0.6mm, Qmin=30"
L7: library part MCD-03457, "Inductor, Wire-wound, 3.6nH, ±0.1nH, 1950mA, 30mR, 0402, T=0.5mm", Manufacturer=MURATA, Package=0402
L8: library part MCD-03456, "Inductor, Wire-wound, 12nHH, ±2%, 500mA, 1405mR, 0402, T=0.5mm", Manufacturer=MURATA, Package=0402
L9: library part MCD-03453, Manufacturer=MURATA, Package=0402
L10: library part MCD-03557, "Inductor, 10uH, +/-20%, 100mA, 1R36, 0805, T=0.8mm", Manufacturer=MURATA, Manufacturer_Part_Number=LQM18DN100M70, Package=0603
L11: library part MCD-01766, "Inductor, 7.5nH, +/-2%, Itemp=460mA max, 0R16, 0402, T= 0.6mm, Qmin=30", Manufacturer=Coilcraft, Manufacturer_Part_Number=0603CS-7N5XJL
L12: library part MCD-01766, "Inductor, 2.7nH, +/-2%, Itemp=460mA max, 0R16, 0402, T= 0.6mm, Qmin=30", Manufacturer=MURATA, Manufacturer_Part_Number=LQG15HN2N7S02D
L13: library part MCD-01766, "Inductor, 27nH, +/-2%, Itemp=460mA max, 0R16, 0402, T= 0.6mm, Qmin=30", Manufacturer=Coilcraft, Manufacturer_Part_Number=0603CS-27NXJL
L14: library part MCD-01766, "Inductor, 15nH, +/-2%, Itemp=460mA max, 0R16, 0402, T= 0.6mm, Qmin=30", Manufacturer=Murata, Manufacturer_Part_Number=LQG15HN15NJ02D, Package=0402
L15: library part MCD-01766, "Inductor, 10nH, +/-2%, Itemp=460mA max, 0R16, 0402, T= 0.6mm, Qmin=30", Manufacturer=Coilcraft, Manufacturer_Part_Number=0603CS-10NXJL, Package=0603
L16: library part MCD-01766, "Inductor, 47nH, +/-2%, Itemp=460mA max, 0R16, 0402, T= 0.6mm, Qmin=30", Manufacturer=Coilcraft, Manufacturer_Part_Number=0603CS-47NXJL
L17: library part MCD-01766, "Inductor, 4.7nH, +/-2%, Itemp=460mA max, 0R16, 0402, T= 0.6mm, Qmin=30", Manufacturer=Murata, Manufacturer_Part_Number=LQG15HN4N7S02D
L18: library part MCD-01766, "0R resistor", Manufacturer=Panasonic, Manufacturer_Part_Number=ERJ3GEJ0R0
L19: library part MCD-01766
L20: library part MCD-01766, "Inductor, 10nH, +/-2%, Itemp=460mA max, 0R16, 0402, T= 0.6mm, Qmin=30", Manufacturer=Murata, Manufacturer_Part_Number=BLM15BD601SN1
L21: library part MCD-01766, "Inductor, 27nH, +/-2%, Itemp=460mA max, 0R16, 0402, T= 0.6mm, Qmin=30", Manufacturer=Murata, Manufacturer_Part_Number=LQG15HN27NJ02D, Package=0402
R1: library part MCD-03301, "0 ohm resistor", Manufacturer=YAGEO, Manufacturer_Part_Number=RC0402JR-070RL, Package=0402
R2: library part MCD-03301, "Resistor, 100K, 0402, +/-1%, 1/16W", Manufacturer=YAGEO, Manufacturer_Part_Number=RT0402FRE07100KL, Package=0402
R3 R4 R5 R6 R7 R8: library part MCD-00481, "Resistor,47R,0402,1%,1/16W", Manufacturer=YAGEO, Manufacturer_Part_Number=RC0402FR-0747RL, Package=R0402
SB1: library part MCD-03219, "Resistor, 0R, 0201, Solder Bridge ON , 1/20W,"
SB2: library part MCD-03219, "Resistor, 0R, 0201, Solder Bridge ON , 1/20W,", Manufacturer=YAGEO, Manufacturer_Part_Number=RC0201JR-070RL, Package=SB0201
SB3 SB4 SB5 SB6 SB7 SB8 SB9 SB11 SB12 SB13 SB14 SB15 SB16 SB17 SB18 SB19 SB20: library part MCD-01618, "Solder Bridge 0402 ON", Manufacturer=YAGEO, Manufacturer_Part_Number=RC0402JR-070RL, Package=SB0402
SC1 SC2 SC3 SC4 SC5 SC6 SC7 SC8 SC9 SC10: library part "Wurth Clip", "shield clip Wurth Elektronik  to fix RF shielded cavity", Manufacturer="Wurth Elektronik", Manufacturer_Part_Number=36900000
U1: library part MCD-03488, "IC, Programmable Sub-1GHz wireless SoC", Manufacturer=STMICROELECTRONICS, Package=QFN48
U2: "169 to 170 MHz Transmit / Receive Front-End  Module for 27 dBm (no BYPASS funct)", Manufacturer=Skyworks, Manufacturer_Part_Number=TBD
X1: library part MCD-01445, "Crystal, 32.768kHz, 7pF, +/-20ppm, 80K, 2.05x1.2mm", Manufacturer=NDK, Manufacturer_Part_Number=NX2012SA-32.768KHZ-EXS00A-MU00389, Package=2.05x1.2mm
X2: library part NT2016SJA, "TCXO 48 MHz  NDK Spec. No.:END6296A", Manufacturer=NDK, Manufacturer_Part_Number=NT2016SJA-END6296A

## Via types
v1: diameter 0.45, hole 0.2, Top Layer to Bottom Layer, tented both sides, 593 vias
v2: diameter 0.45, hole 0.3, Top Layer to Bottom Layer, tented both sides, 28 vias

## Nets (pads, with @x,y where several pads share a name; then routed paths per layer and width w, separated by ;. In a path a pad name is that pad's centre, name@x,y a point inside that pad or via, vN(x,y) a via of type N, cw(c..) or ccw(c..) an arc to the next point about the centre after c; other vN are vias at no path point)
"ANT Path": C2.2 C38.2 L1.1 L18.2 R1.1 | length 5.4
  Top Layer w0.44: L18.2@21.5,47.252 C38.2@21.5,48.254 21.5,50.798 ; C2.2@21.5,51.525 L1.1@21.5,52.325 L1.1@21.5,52.336 ; R1.1@21.506,50.475 C2.2@21.506,51.525
CSD: SB11.2 U1.11 U2.1 | length 66.8
  Top Layer w0.15: v1@16.183,38.682 U2.1@16.773,38.682 ; U1.11@26.125,25.25 27.218,25.25 27.268,25.2 28.926,25.2 29.126,25.4 v1(29.15,25.4)
  Top Layer w0.43: v1(16.18,38.684) v1@16.183,38.682
  Signal Layer 2 w0.15: v1(16.18,38.684) 17.168,38.684 18.153,37.699 18.241,37.612 18.241,36.492 19.557,35.176 19.557,33.083 18.193,31.718 18.193,28.596 18.639,28.149 19.506,28.149 22.816,28.149 cw(c22.816,27.999) 22.922,28.105 23.142,27.886 23.142,27.294 23.43,27.005 28.075,27.005 29.15,25.93 v1(29.15,25.4) 31.177,25.4 32.995,27.218 39.257,27.218 39.594,26.881 39.594,9.932 38.862,9.2 38.021,9.2 36.008,7.187 v1(32.1,7.187)
  Bottom Layer w0.15: v1(32.1,7.187) SB11.2@32.725,7.187
CTX: SB20.1 U1.19 U2.3 | length 86.1
  Top Layer w0.15: U2.3@18.475,38.68 18.508,38.647 18.508,37.981 v1(18.541,37.948) ; U1.19@23.15,26.225 23.15,26.878 cw(c23.3,26.878) 23.194,26.984 v1(23.718,27.509) ; v1(38.672,28.273) 39.296,27.649 39.296,8.471 v1(38.675,7.85)
  Signal Layer 2 w0.15: v1(10.895,7.666) 13.138,7.666 13.323,7.85 30.4,7.85 31.598,6.652 36.102,6.652 37.3,7.85 v1(38.675,7.85) ; v1@18.492,37.899 v1(18.541,37.948) 18.541,36.616 19.857,35.3 19.857,32.959 18.492,31.594 18.492,28.72 18.764,28.449 23.273,28.449 23.718,28.004 v1(23.718,27.509) 24.37,27.509 25.281,28.42 26.98,28.42 27.362,28.038 28.228,28.038 28.611,28.42 29.143,28.42 29.526,28.038 30.66,28.038 31.178,28.555 35.64,28.555 35.923,28.273 v1(38.672,28.273)
  Bottom Layer w0.2: SB20.1@9.749,8.38 10.181,8.38 v1(10.895,7.666)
